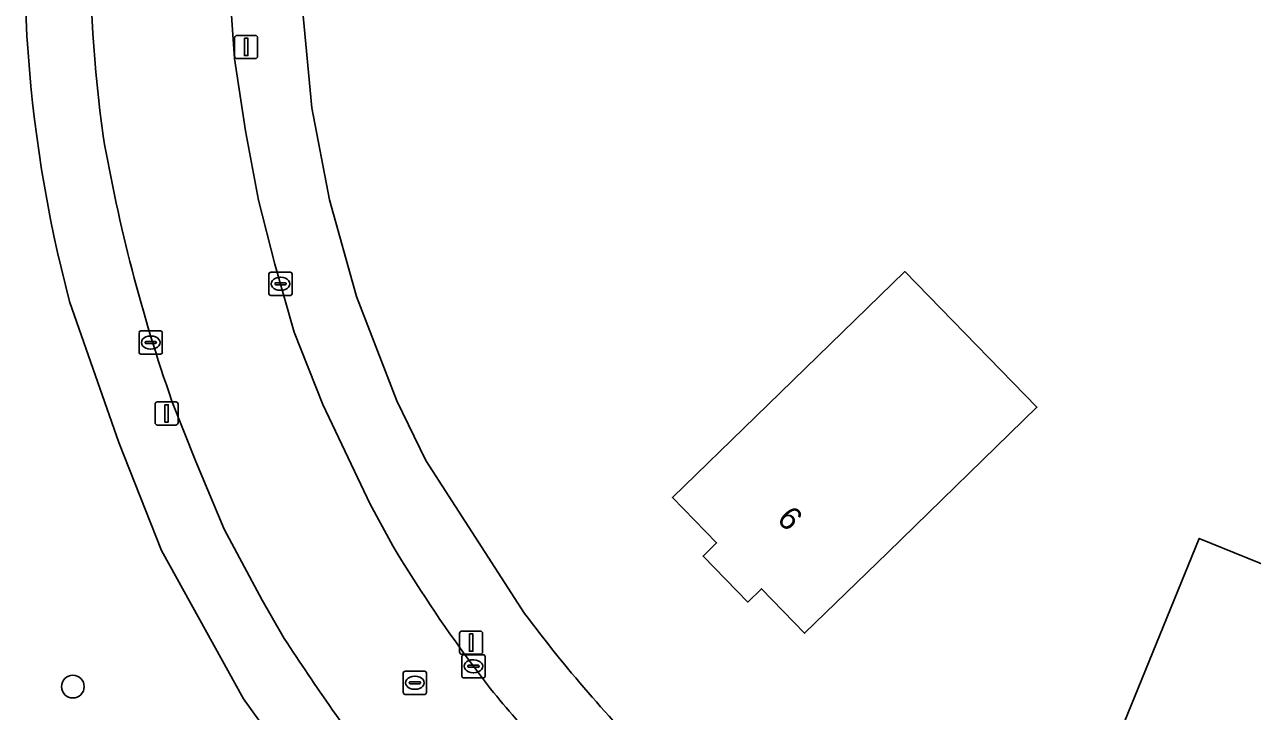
# Model space of a CAD drawing. Extents: x 161139 to 161601, y 381708 to 382245.
# Drawn here: x 161255.5 to 161308.4, y 381899.5 to 381929.2 of the extents above; entities that cross this region are included whole.
import ezdxf

# ---------------------------------------------------------------- set-up
doc = ezdxf.new("R2010")
doc.units = 0
for name, color, linetype in [('IMGEO_Boom', 7, 'Continuous'), ('IMGEO_Erf', 7, 'Continuous'), ('IMGEO_Groenvoorziening', 7, 'Continuous'), ('IMGEO_Kolk', 7, 'Continuous'), ('IMGEO_Lichtmast', 7, 'Continuous'), ('IMGEO_Pand', 7, 'Continuous'), ('IMGEO_Pand_nummerreeks', 7, 'Continuous'), ('IMGEO_Rijbaan_lokaal_open', 7, 'Continuous'), ('IMGEO_Rioolput', 7, 'Continuous'), ('IMGEO_Voetpad_open', 7, 'Continuous')]:
    doc.layers.add(name, color=color, linetype=linetype)

msp = doc.modelspace()

# ---------------------------------------------------------------- linework, layer by layer
at = {"layer": 'IMGEO_Boom'}
msp.add_circle((161257.561, 381900.613), 0.489, dxfattribs=at)
at = {"layer": 'IMGEO_Erf'}
msp.add_lwpolyline([(161370.462, 381928.258), (161276.309, 381989.126), (161276.14, 381989.025), (161267.873, 381937.797), (161267.435, 381933.784), (161267.467, 381929.855), (161267.871, 381925.589), (161268.634, 381921.624), (161269.796, 381917.444), (161271.533, 381912.948), (161272.783, 381910.378), (161277.045, 381903.774)], dxfattribs=at)
for points in [[(161289.127, 381902.92), (161287.265, 381904.835), (161286.675, 381904.261), (161284.744, 381906.246), (161285.326, 381906.813), (161283.423, 381908.769), (161287.007, 381912.256), (161293.446, 381918.522), (161299.144, 381912.667), (161292.711, 381906.407)], [(161316.193, 381910.265), (161323.278, 381907.381), (161321.194, 381902.259), (161317.489, 381903.766), (161313.947, 381895.06), (161312.062, 381890.428), (161305.111, 381893.257), (161305.8, 381894.95), (161305.424, 381895.103), (161305.852, 381896.154), (161306.302, 381895.986), (161306.706, 381897.067), (161302.753, 381898.676), (161306.145, 381907.012), (161310.258, 381905.339), (161309.82, 381904.264), (161313.34, 381902.832), (161314.245, 381905.055), (161314.097, 381905.115)]]:
    msp.add_lwpolyline(points, close=True, dxfattribs=at)
msp.add_arc((161325.918, 381940.222), 60.967, 216.71398, 224.93243, dxfattribs=at)
at = {"layer": 'IMGEO_Groenvoorziening'}
for points in [[(161261.387, 381906.491), (161259.539, 381911.147), (161257.417, 381917.229)], [(161272.651, 381890.451), (161268.63, 381894.919), (161264.924, 381900.093), (161261.387, 381906.491)]]:
    msp.add_lwpolyline(points, dxfattribs=at)
msp.add_arc((161314.162, 381932.197), 58.686, 172.06408, 194.77714, dxfattribs=at)
at = {"layer": 'IMGEO_Kolk'}
for p, q in [((161266.018, 381917.569), (161266.018, 381918.421)), ((161266.093, 381918.495), (161266.945, 381918.495)), ((161266.277, 381917.989), (161266.277, 381918.001)), ((161266.32, 381918.038), (161266.718, 381918.038)), ((161266.506, 381918.275), (161266.531, 381918.275)), ((161266.761, 381918.001), (161266.761, 381917.989)), ((161267.019, 381918.421), (161267.019, 381917.569)), ((161266.945, 381917.495), (161266.093, 381917.495)), ((161266.715, 381917.952), (161266.317, 381917.952)), ((161266.529, 381917.715), (161266.504, 381917.715)), ((161260.418, 381915.035), (161260.418, 381915.887)), ((161260.493, 381915.961), (161261.345, 381915.961)), ((161261.419, 381915.887), (161261.419, 381915.035)), ((161260.677, 381915.455), (161260.677, 381915.467)), ((161261.115, 381915.418), (161260.717, 381915.418)), ((161260.72, 381915.504), (161261.118, 381915.504)), ((161260.906, 381915.741), (161260.931, 381915.741)), ((161261.161, 381915.467), (161261.161, 381915.455)), ((161261.345, 381914.961), (161260.493, 381914.961)), ((161260.929, 381915.181), (161260.904, 381915.181)), ((161274.34, 381901.067), (161274.34, 381901.919)), ((161274.415, 381901.993), (161275.267, 381901.993)), ((161274.828, 381901.773), (161274.853, 381901.773)), ((161275.341, 381901.919), (161275.341, 381901.067)), ((161274.599, 381901.487), (161274.599, 381901.499)), ((161275.037, 381901.45), (161274.639, 381901.45)), ((161274.642, 381901.536), (161275.04, 381901.536)), ((161274.851, 381901.213), (161274.826, 381901.213)), ((161275.083, 381901.499), (161275.083, 381901.487)), ((161275.267, 381900.993), (161274.415, 381900.993))]:
    msp.add_line(p, q, dxfattribs=at)
for points in [[(161266.018, 381917.569), (161266.018, 381918.421)], [(161266.093, 381918.495), (161266.945, 381918.495)], [(161267.019, 381918.421), (161267.019, 381917.569)], [(161266.945, 381917.495), (161266.093, 381917.495)], [(161260.418, 381915.035), (161260.418, 381915.887)], [(161260.493, 381915.961), (161261.345, 381915.961)], [(161261.419, 381915.887), (161261.419, 381915.035)], [(161261.345, 381914.961), (161260.493, 381914.961)], [(161274.34, 381901.067), (161274.34, 381901.919)], [(161274.415, 381901.993), (161275.267, 381901.993)], [(161275.341, 381901.919), (161275.341, 381901.067)], [(161275.267, 381900.993), (161274.415, 381900.993)]]:
    msp.add_lwpolyline(points, dxfattribs=at)
for centre, radius, start, end in [((161266.095, 381918.419), 0.0765, 91.552, 178.448), ((161266.095, 381918.419), 0.0765, 91.552, 178.448), ((161266.317, 381917.998), 0.0403, 85.8775, 175.7526), ((161266.722, 381918), 0.0386, 1.7309, 96.639), ((161266.943, 381918.419), 0.0765, 1.552, 88.448), ((161266.943, 381918.419), 0.0765, 1.552, 88.448), ((161266.095, 381917.571), 0.0765, 181.552, 268.448), ((161266.095, 381917.571), 0.0765, 181.552, 268.448), ((161266.314, 381917.988), 0.0366, 178.938, 274.7102), ((161266.718, 381917.995), 0.043, 264.8664, 352.4533), ((161266.943, 381917.571), 0.0765, 271.552, 358.448), ((161266.943, 381917.571), 0.0765, 271.552, 358.448), ((161260.495, 381915.885), 0.0765, 91.552, 178.448), ((161260.495, 381915.885), 0.0765, 91.552, 178.448), ((161261.343, 381915.885), 0.0765, 1.552, 88.448), ((161261.343, 381915.885), 0.0765, 1.552, 88.448), ((161260.717, 381915.464), 0.0403, 85.8775, 175.7526), ((161260.714, 381915.454), 0.0366, 178.938, 274.7102), ((161261.118, 381915.461), 0.043, 264.8664, 352.4533), ((161261.122, 381915.466), 0.0386, 1.7309, 96.639), ((161260.495, 381915.037), 0.0765, 181.552, 268.448), ((161260.495, 381915.037), 0.0765, 181.552, 268.448), ((161261.343, 381915.037), 0.0765, 271.552, 358.448), ((161261.343, 381915.037), 0.0765, 271.552, 358.448), ((161274.417, 381901.917), 0.0765, 91.552, 178.448), ((161274.417, 381901.917), 0.0765, 91.552, 178.448), ((161275.265, 381901.917), 0.0765, 1.552, 88.448), ((161275.265, 381901.917), 0.0765, 1.552, 88.448), ((161274.417, 381901.069), 0.0765, 181.552, 268.448), ((161274.417, 381901.069), 0.0765, 181.552, 268.448), ((161274.639, 381901.496), 0.0403, 85.8775, 175.7526), ((161274.636, 381901.486), 0.0366, 178.938, 274.7102), ((161275.04, 381901.493), 0.043, 264.8664, 352.4533), ((161275.044, 381901.498), 0.0386, 1.7309, 96.639), ((161275.265, 381901.069), 0.0765, 271.552, 358.448), ((161275.265, 381901.069), 0.0765, 271.552, 358.448)]:
    msp.add_arc(centre, radius, start, end, dxfattribs=at)
for centre, major_axis, ratio, start_param, end_param in [((161266.505, 381917.995), (-0.387, 0.002), 0.722429, 4.712389, 7.853982), ((161266.53, 381917.995), (-0.39, 0.002), 0.717154, 1.570796, 4.712389), ((161260.905, 381915.461), (-0.387, 0.002), 0.722429, 4.712389, 7.853982), ((161260.93, 381915.461), (-0.39, 0.002), 0.717154, 1.570796, 4.712389), ((161274.827, 381901.493), (-0.387, 0.002), 0.722429, 4.712389, 7.853982), ((161274.852, 381901.493), (-0.39, 0.002), 0.717154, 1.570796, 4.712389)]:
    msp.add_ellipse(centre, major_axis=major_axis, ratio=ratio, start_param=start_param, end_param=end_param, dxfattribs=at)
at = {"layer": 'IMGEO_Lichtmast'}
for p, q in [((161264.539, 381927.815), (161264.539, 381928.615)), ((161264.539, 381928.615), (161264.539, 381927.815)), ((161264.639, 381928.715), (161265.429, 381928.715)), ((161265.429, 381928.715), (161264.639, 381928.715)), ((161265.529, 381928.615), (161265.529, 381927.815)), ((161265.529, 381927.815), (161265.529, 381928.615)), ((161265.429, 381927.715), (161264.639, 381927.715)), ((161264.639, 381927.715), (161265.429, 381927.715)), ((161261.107, 381912.003), (161261.107, 381912.803)), ((161261.107, 381912.803), (161261.107, 381912.003)), ((161261.207, 381912.903), (161261.997, 381912.903)), ((161261.997, 381912.903), (161261.207, 381912.903)), ((161262.097, 381912.803), (161262.097, 381912.003)), ((161262.097, 381912.003), (161262.097, 381912.803)), ((161261.997, 381911.903), (161261.207, 381911.903)), ((161261.207, 381911.903), (161261.997, 381911.903)), ((161274.244, 381902.114), (161274.244, 381902.914)), ((161274.244, 381902.914), (161274.244, 381902.114)), ((161274.344, 381903.014), (161275.134, 381903.014)), ((161275.134, 381903.014), (161274.344, 381903.014)), ((161275.234, 381902.914), (161275.234, 381902.114)), ((161275.234, 381902.114), (161275.234, 381902.914)), ((161275.134, 381902.014), (161274.344, 381902.014)), ((161274.344, 381902.014), (161275.134, 381902.014))]:
    msp.add_line(p, q, dxfattribs=at)
for points in [[(161264.959, 381928.59), (161265.109, 381928.59), (161265.109, 381927.84), (161264.959, 381927.84), (161264.959, 381928.59)], [(161261.527, 381912.778), (161261.677, 381912.778), (161261.677, 381912.028), (161261.527, 381912.028), (161261.527, 381912.778)], [(161274.664, 381902.889), (161274.814, 381902.889), (161274.814, 381902.139), (161274.664, 381902.139), (161274.664, 381902.889)]]:
    msp.add_lwpolyline(points, dxfattribs=at)
for centre, start, end in [((161264.639, 381928.615), 90, 180), ((161264.639, 381928.615), 90, 180), ((161265.429, 381928.615), 0, 90), ((161265.429, 381928.615), 360, 90), ((161264.639, 381927.815), 180, 270), ((161264.639, 381927.815), 180, 270), ((161265.429, 381927.815), 270, 0), ((161265.429, 381927.815), 270, 0), ((161261.207, 381912.803), 90, 180), ((161261.207, 381912.803), 90, 180), ((161261.997, 381912.803), 0, 90), ((161261.997, 381912.803), 360, 90), ((161261.207, 381912.003), 180, 270), ((161261.207, 381912.003), 180, 270), ((161261.997, 381912.003), 270, 0), ((161261.997, 381912.003), 270, 0), ((161274.344, 381902.914), 90, 180), ((161274.344, 381902.914), 90, 180), ((161275.134, 381902.914), 0, 90), ((161275.134, 381902.914), 360, 90), ((161274.344, 381902.114), 180, 270), ((161274.344, 381902.114), 180, 270), ((161275.134, 381902.114), 270, 0), ((161275.134, 381902.114), 270, 0)]:
    msp.add_arc(centre, 0.1, start, end, dxfattribs=at)
at = {"layer": 'IMGEO_Pand'}
for points in [[(161287.007, 381912.256), (161283.423, 381908.769), (161285.326, 381906.813), (161284.744, 381906.246), (161286.675, 381904.261), (161287.265, 381904.835), (161289.127, 381902.92), (161292.711, 381906.407), (161299.144, 381912.667), (161293.446, 381918.522)], [(161312.062, 381890.428), (161313.947, 381895.06), (161317.489, 381903.766), (161321.194, 381902.259), (161323.278, 381907.381), (161316.193, 381910.265), (161314.097, 381905.115), (161314.245, 381905.055), (161313.34, 381902.832), (161309.82, 381904.264), (161310.258, 381905.339), (161306.145, 381907.012), (161302.753, 381898.676), (161306.706, 381897.067), (161306.302, 381895.986), (161305.852, 381896.154), (161305.424, 381895.103), (161305.8, 381894.95), (161305.111, 381893.257)]]:
    msp.add_lwpolyline(points, close=True, dxfattribs=at)
at = {"layer": 'IMGEO_Rijbaan_lokaal_open'}
for points in [[(161265.564, 381921.601), (161265, 381924.596), (161264.526, 381927.722), (161264.331, 381930.62), (161264.405, 381933.991), (161264.554, 381936.602), (161264.932, 381939.304), (161265.288, 381942.157), (161265.934, 381946.371), (161266.311, 381948.744), (161267.185, 381954.246), (161268.219, 381960.609), (161269.186, 381967.075), (161270.456, 381974.554), (161271.16, 381978.342), (161273.075, 381989.612), (161273.208, 381990.334), (161267.316, 381991.303), (161259.178, 381942.049)], [(161271.356, 381906.689), (161270.379, 381908.492), (161268.344, 381912.783), (161267.11, 381915.904), (161266.277, 381918.847), (161265.564, 381921.601)], [(161261.835, 381912.934), (161262.866, 381910.322), (161264.089, 381907.412), (161265.722, 381904.345), (161266.554, 381902.888)], [(161275.576, 381900.526), (161274.707, 381901.67)]]:
    msp.add_lwpolyline(points, dxfattribs=at)
for centre, radius, start, end in [((161315.125, 381932.225), 56.803, 170.0404, 187.9434), ((161329.155, 381936.504), 71.327, 189.79024, 199.2957), ((161327.716, 381940.691), 65.822, 211.10209, 216.35704), ((161357.146, 381961.507), 107.903, 212.90543, 216.8632), ((161305.516, 381924.595), 38.415, 218.7964, 223.8402)]:
    msp.add_arc(centre, radius, start, end, dxfattribs=at)
at = {"layer": 'IMGEO_Rioolput'}
for p, q in [((161271.813, 381900.354), (161271.813, 381901.206)), ((161271.888, 381901.28), (161272.74, 381901.28)), ((161272.301, 381901.06), (161272.326, 381901.06)), ((161272.814, 381901.206), (161272.814, 381900.354)), ((161272.072, 381900.774), (161272.072, 381900.786)), ((161272.51, 381900.737), (161272.112, 381900.737)), ((161272.115, 381900.823), (161272.513, 381900.823)), ((161272.556, 381900.786), (161272.556, 381900.774)), ((161272.74, 381900.28), (161271.888, 381900.28)), ((161272.324, 381900.5), (161272.299, 381900.5))]:
    msp.add_line(p, q, dxfattribs=at)
for points in [[(161271.813, 381900.354), (161271.813, 381901.206)], [(161271.888, 381901.28), (161272.74, 381901.28)], [(161272.814, 381901.206), (161272.814, 381900.354)], [(161272.74, 381900.28), (161271.888, 381900.28)]]:
    msp.add_lwpolyline(points, dxfattribs=at)
for centre, radius, start, end in [((161271.89, 381901.204), 0.0765, 91.552, 178.448), ((161271.89, 381901.204), 0.0765, 91.552, 178.448), ((161272.738, 381901.204), 0.0765, 1.552, 88.448), ((161272.738, 381901.204), 0.0765, 1.552, 88.448), ((161272.112, 381900.783), 0.0403, 85.8775, 175.7526), ((161272.109, 381900.773), 0.0366, 178.938, 274.7102), ((161272.513, 381900.78), 0.043, 264.8664, 352.4533), ((161272.517, 381900.785), 0.0386, 1.7309, 96.639), ((161271.89, 381900.356), 0.0765, 181.552, 268.448), ((161271.89, 381900.356), 0.0765, 181.552, 268.448), ((161272.738, 381900.356), 0.0765, 271.552, 358.448), ((161272.738, 381900.356), 0.0765, 271.552, 358.448)]:
    msp.add_arc(centre, radius, start, end, dxfattribs=at)
for centre, major_axis, ratio, start_param, end_param in [((161272.3, 381900.78), (-0.387, 0.002), 0.722429, 4.712389, 7.853982), ((161272.325, 381900.78), (-0.39, 0.002), 0.717154, 1.570796, 4.712389)]:
    msp.add_ellipse(centre, major_axis=major_axis, ratio=ratio, start_param=start_param, end_param=end_param, dxfattribs=at)
at = {"layer": 'IMGEO_Voetpad_open'}
for points in [[(161273.208, 381990.334), (161273.075, 381989.612), (161271.16, 381978.342), (161270.456, 381974.554), (161269.186, 381967.075), (161268.219, 381960.609), (161267.185, 381954.246), (161266.311, 381948.744), (161265.934, 381946.371), (161265.288, 381942.157), (161264.932, 381939.304), (161264.554, 381936.602), (161264.405, 381933.991), (161264.331, 381930.62), (161264.526, 381927.722), (161265, 381924.596), (161265.564, 381921.601), (161266.277, 381918.847), (161267.11, 381915.904), (161268.344, 381912.783), (161270.379, 381908.492), (161271.356, 381906.689)], [(161277.045, 381903.774), (161272.783, 381910.378), (161271.533, 381912.948), (161269.796, 381917.444), (161268.634, 381921.624), (161267.871, 381925.589), (161267.467, 381929.855), (161267.435, 381933.784), (161267.873, 381937.797), (161276.14, 381989.025)], [(161257.417, 381917.229), (161259.539, 381911.147), (161261.387, 381906.491), (161264.924, 381900.093), (161268.63, 381894.919), (161272.651, 381890.451)], [(161266.554, 381902.888), (161265.722, 381904.345), (161264.089, 381907.412), (161262.866, 381910.322), (161261.835, 381912.934)], [(161274.707, 381901.67), (161275.576, 381900.526)]]:
    msp.add_lwpolyline(points, dxfattribs=at)
for centre, radius, start, end in [((161315.125, 381932.225), 56.803, 170.0404, 187.9434), ((161314.162, 381932.197), 58.686, 172.06408, 194.77714), ((161329.155, 381936.504), 71.327, 189.79024, 199.2957), ((161327.716, 381940.691), 65.822, 211.10209, 216.35704), ((161325.918, 381940.222), 60.967, 216.71398, 224.93243), ((161357.146, 381961.507), 107.903, 212.90543, 216.8632), ((161305.516, 381924.595), 38.415, 218.7964, 223.8402)]:
    msp.add_arc(centre, radius, start, end, dxfattribs=at)

# ---------------------------------------------------------------- texts
at = {"layer": 'IMGEO_Pand_nummerreeks'}
msp.add_text('6', height=1, rotation=314.2809, dxfattribs=at).set_placement((161287.887, 381907.8))

doc.saveas('drawing.dxf')
